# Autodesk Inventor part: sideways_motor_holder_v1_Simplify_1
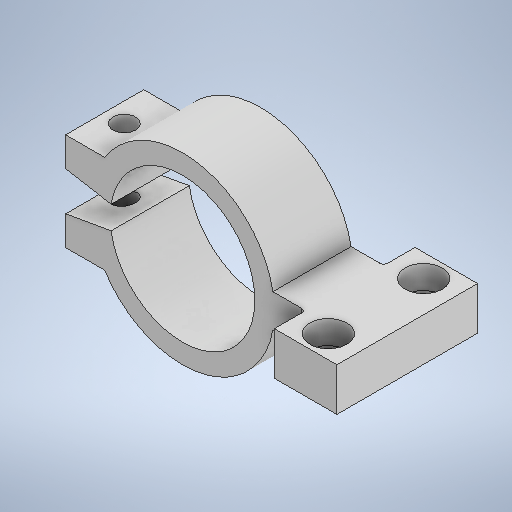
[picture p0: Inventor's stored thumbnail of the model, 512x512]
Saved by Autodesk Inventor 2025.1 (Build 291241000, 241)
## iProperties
Created: 2024-11
Part Number: sideways_motor_holder_v1_Simplify_1
Material: Generic
Document SubType Name: Modeling
Designer: mansa
Density: 1 g/cm^3
Appearance: Default
Author: mansa
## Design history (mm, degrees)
derived "sideways_motor_holder_v1.iam"
fillet "Fillet1" dims "d1" = 1
body "Solid1"
node "motor holder_side_v1.ipt:1" dims "d0" = 10
node "basic_frame_screw_mount.ipt:1" dims "d0" = 10
node "sideways_motor_holder_v1.iam_Bodies" dims "d0" = 10
